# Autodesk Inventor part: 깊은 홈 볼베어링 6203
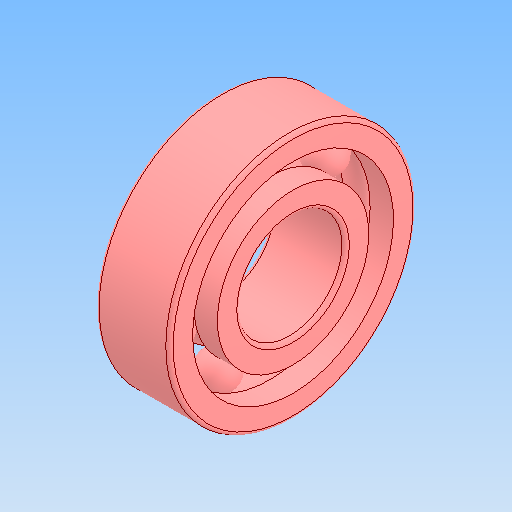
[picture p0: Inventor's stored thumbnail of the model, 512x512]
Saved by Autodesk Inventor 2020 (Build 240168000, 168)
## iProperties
Created: 2024-09
Part Number: 깊은 홈 볼베어링 6203
Material: 강철, 연강
Description: 깊은 그루브 볼 베어링
Document SubType Name: Modeling
Designer: oem
Density: 7.85 g/cm^3
Appearance: 기본값
Author: jhkim
Sending System: Autodesk Inventor 2025
Preprocessor: ST-DEVELOPER v20
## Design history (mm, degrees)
feature "Solid1"
feature "Solid1:1"
feature "Solid1:2"
feature "Solid1:3"
feature "Solid1:4"
feature "Solid1:5"
feature "Solid1:6"
feature "Solid1:7"
feature "Solid1:8"
node "솔리드1"
node "솔리드2"
node "솔리드3"
node "솔리드4"
node "솔리드5"
node "솔리드6"
node "솔리드7"
node "솔리드8"
node "솔리드9"
